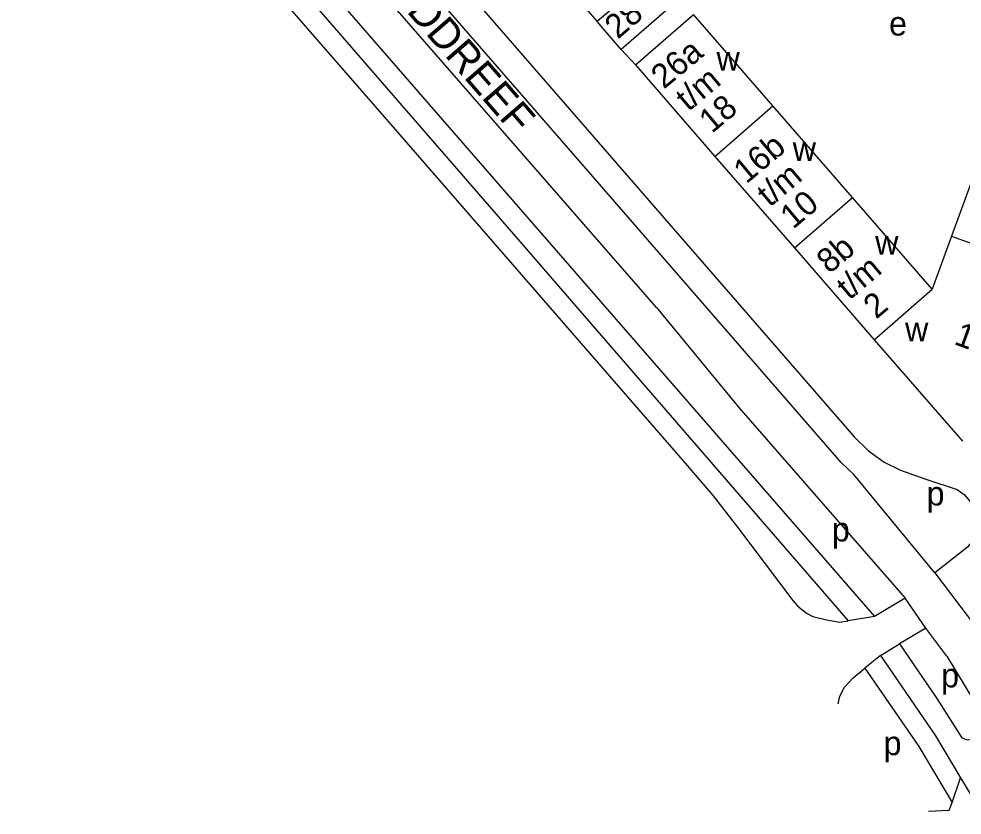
# Model space of a CAD drawing. Extents: x 155854 to 157362, y 383621 to 384685.
# Drawn here: x 156509.5 to 156666.3, y 383844.7 to 383977 of the extents above; entities that cross this region are included whole.
import ezdxf

# ---------------------------------------------------------------- set-up
doc = ezdxf.new("R2010")
doc.units = 0
for name, color, linetype in [('BLT_Basislijn', 7, 'Continuous'), ('BLT_Bebouwing', 7, 'Continuous'), ('BLT_Centroide', 7, 'Continuous'), ('BLT_Huisnummer', 7, 'Continuous'), ('BLT_Huisnummer_reeks', 7, 'Continuous'), ('BLT_Onderverdeling_panden', 7, 'Continuous'), ('BLT_Straatnaam', 7, 'Continuous'), ('BLT_Vlakafsluiter', 7, 'Continuous')]:
    doc.layers.add(name, color=color, linetype=linetype)

msp = doc.modelspace()

# ---------------------------------------------------------------- linework, layer by layer
at = {"layer": 'BLT_Basislijn'}
for p, q in [((156615.46, 383929.06), (156519.5, 384039.14)), ((156514.79, 384035.14), (156576.58, 383964.1)), ((156604.15, 383951.65), (156531.14, 384035.69)), ((156509.49, 384030.65), (156571.29, 383959.5)), ((156609.6, 383971.97), (156611.96, 383969.4)), ((156576.58, 383964.1), (156651.7, 383877.75)), ((156646.14, 383903.32), (156604.15, 383951.65)), ((156646.14, 383903.32), (156648.26, 383901.33)), ((156661.72, 383884.98), (156648.26, 383901.33)), ((156652.69, 383871.23), (156655.83, 383873.22)), ((156652.69, 383871.23), (156650.11, 383869.15)), ((156663.7, 383871.15), (156669.79, 383861.04)), ((156664.63, 383846.84), (156666.02, 383850.93)), ((156666.02, 383850.93), (156669.74, 383844.74))]:
    msp.add_line(p, q, dxfattribs=at)
for points in [[(156528.74, 384045.23), (156648.34, 383907.58)], [(156513.03, 384032.01), (156540.77, 383999.98), (156592.43, 383940.41), (156647.3, 383877.04)], [(156571.29, 383959.5), (156620.54, 383902.82), (156624.86, 383897.8), (156628.93, 383892.58), (156633.55, 383886.51), (156638.12, 383880.41), (156638.84, 383879.58), (156639.63, 383878.89), (156640.49, 383878.26), (156641.44, 383877.75), (156643.71, 383877.16), (156645.93, 383876.8), (156647.3, 383877.04)], [(156615.46, 383929.06), (156629.13, 383912.48)], [(156629.13, 383912.48), (156656.82, 383880.81)], [(156648.34, 383907.58), (156650.73, 383905.27), (156653.33, 383903.36), (156656.02, 383902.06), (156660.22, 383900.56), (156665.45, 383898.82), (156666.67, 383897.95), (156667.72, 383896.7), (156668.42, 383895.38), (156668.79, 383893.79), (156668.78, 383892.59), (156668.46, 383891.35), (156667.94, 383890.28), (156667.16, 383889.25), (156661.72, 383884.98)], [(156656.82, 383880.81), (156651.7, 383877.75)], [(156665.87, 383879.49), (156669.71, 383874.45), (156676.22, 383863.18)], [(156660.24, 383875.81), (156655.83, 383873.22)], [(156663.7, 383871.15), (156660.24, 383875.81)], [(156655.83, 383873.22), (156662.04, 383864.13)], [(156652.69, 383871.23), (156661.84, 383857.9), (156666.02, 383850.93)], [(156645.65, 383863.24), (156645.94, 383864.5), (156646.72, 383865.99), (156648.13, 383867.57), (156650.11, 383869.15)], [(156650.11, 383869.15), (156659.06, 383856.12), (156664.63, 383846.84)], [(156662.04, 383864.13), (156666.23, 383857.56)], [(156666.23, 383857.56), (156667.18, 383857.27), (156667.87, 383857.35), (156668.55, 383857.69), (156669.79, 383861.04)], [(156660.65, 383845.41), (156664.12, 383845.58), (156664.63, 383846.84)]]:
    msp.add_lwpolyline(points, dxfattribs=at)
at = {"layer": 'BLT_Bebouwing'}
for p, q in [((156601.64, 383981.15), (156605.6, 383976.58)), ((156619.23, 383980.36), (156609.6, 383971.97)), ((156609.6, 383971.97), (156605.6, 383976.58)), ((156634.83, 383962.56), (156621.61, 383977.77)), ((156611.96, 383969.4), (156625.17, 383954.19)), ((156648.05, 383947.35), (156634.83, 383962.56)), ((156671.05, 383958.93), (156664.51, 383940.92)), ((156625.17, 383954.19), (156638.39, 383938.98)), ((156661.3, 383932.11), (156648.05, 383947.35)), ((156664.51, 383940.92), (156661.3, 383932.11)), ((156638.39, 383938.98), (156651.65, 383923.72)), ((156651.65, 383923.72), (156666.3, 383906.85))]:
    msp.add_line(p, q, dxfattribs=at)
msp.add_lwpolyline([(156611.96, 383969.4), (156621.61, 383977.77)], dxfattribs=at)
at = {"layer": 'BLT_Onderverdeling_panden'}
for p, q in [((156615.26, 383984.98), (156605.6, 383976.58)), ((156625.17, 383954.19), (156634.83, 383962.56)), ((156638.39, 383938.98), (156648.05, 383947.35)), ((156664.51, 383940.92), (156677.02, 383936.37)), ((156651.65, 383923.72), (156661.3, 383932.11))]:
    msp.add_line(p, q, dxfattribs=at)
at = {"layer": 'BLT_Vlakafsluiter'}
for p, q in [((156661.72, 383884.98), (156665.87, 383879.49)), ((156660.24, 383875.81), (156656.82, 383880.81)), ((156651.7, 383877.75), (156647.3, 383877.04))]:
    msp.add_line(p, q, dxfattribs=at)

# ---------------------------------------------------------------- texts
at = {"layer": 'BLT_Centroide'}
for s, p in [('e', (156654.12, 383974.26)), ('w', (156625.44, 383968.45)), ('w', (156638.11, 383953.44)), ('w', (156651.81, 383937.87)), ('w', (156656.78, 383923.48)), ('p', (156660.36, 383896.18)), ('p', (156644.62, 383890.21)), ('p', (156662.78, 383865.96)), ('p', (156653.21, 383854.7))]:
    msp.add_text(s, height=4, dxfattribs=at).set_placement(p)
at = {"layer": 'BLT_Huisnummer'}
msp.add_text('28', height=4, rotation=40.9834, dxfattribs=at).set_placement((156609.04, 383973.54))
at = {"layer": 'BLT_Huisnummer_reeks'}
for s, rotation, p in [('26a', 40.0266, (156616.69, 383965.25)), ('t/m', 40.0266, (156620.77, 383961.54)), ('18', 40.0266, (156624.66, 383957.89)), ('16b', 40.0266, (156630.39, 383949.51)), ('t/m', 40.0266, (156634.28, 383945.64)), ('10', 40.0266, (156638.16, 383941.98)), ('8b', 40.0266, (156644.2, 383934.56)), ('t/m', 40.0266, (156647.51, 383930.2)), ('2', 40.0266, (156651.98, 383927.04)), ('190', 340.0266, (156664.73, 383923.04))]:
    msp.add_text(s, height=4, rotation=rotation, dxfattribs=at).set_placement(p)
at = {"layer": 'BLT_Straatnaam'}
msp.add_text('ZANDDREEF', height=5, rotation=310.9827, dxfattribs=at).set_placement((156565.05, 383988.34))

doc.saveas('drawing.dxf')
